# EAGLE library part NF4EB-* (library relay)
FLATPACK RELAY NAiS Source: http://www.mew-europe.com/.. en_ds_61014_0000.pdf
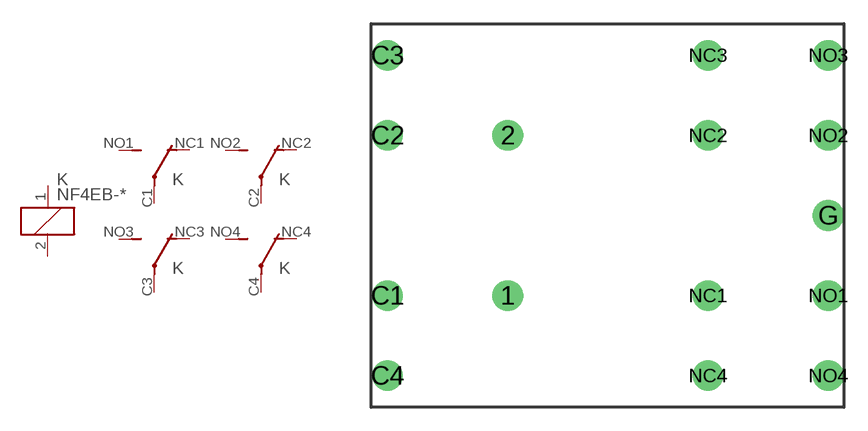
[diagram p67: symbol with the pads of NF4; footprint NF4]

Designator prefix K; gates _=K 1=U 2=U 3=U 4=U

## NF4EB-5V (MPN: NF4EB-5V; OC_FARNELL: 1200947; OC_NEWARK: 13P5543), NF4EB-6V (MF: AROMAT/ MATSUSHITA; MPN: NF4EB-6V; OC_FARNELL: unknown; OC_NEWARK: 46F5739), NF4EB-12V (MPN: NF4EB-12V; OC_FARNELL: 1175715; OC_NEWARK: 13P5540), NF4EB-24V (MPN: NF4EB-24V; OC_FARNELL: 1373470; OC_NEWARK: 13P5541), NF4EB-48V (MPN: NF4EB-48V; OC_FARNELL: unknown; OC_NEWARK: 13P5542)  [NF4]
1  _:1  pas
2  _:2  pas
C1  1:P  pas
C2  2:P  pas
C3  3:P  pas
C4  4:P  pas
NC1  1:O  pas
NC2  2:O  pas
NC3  3:O  pas
NC4  4:O  pas
NO1  1:S  pas
NO2  2:S  pas
NO3  3:S  pas
NO4  4:S  pas

## Footprint NF4 (pad centres in mm)
FLATPACK RELAY NAiS Source: http://www.mew-europe.com/.. en_ds_61014_0000.pdf
drill 1.3 round: 1 -6.35,-5.08; 2 -6.35,5.08; C1 -13.97,-5.08; C2 -13.97,5.08; C3 -13.97,10.16; C4 -13.97,-10.16; G 13.97,0; NC1 6.35,-5.08; NC2 6.35,5.08; NC3 6.35,10.16; NC4 6.35,-10.16; NO1 13.97,-5.08; NO2 13.97,5.08; NO3 13.97,10.16; NO4 13.97,-10.16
